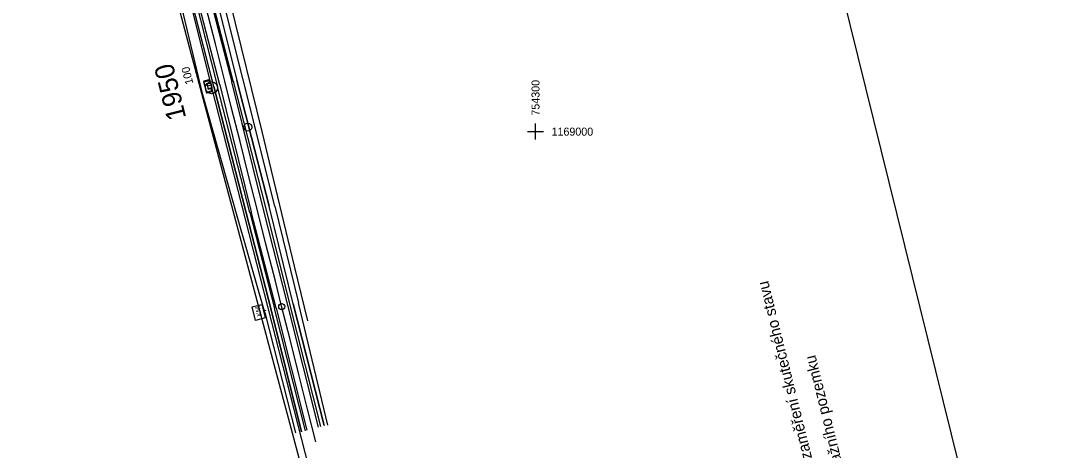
# Model space of a CAD drawing. Extents: x -754679 to -754173, y -1169241 to -1168288.
# Drawn here: x -754428.7 to -754172.8, y -1169079.6 to -1168972.2 of the extents above; entities that cross this region are included whole.
import ezdxf

# ---------------------------------------------------------------- set-up
doc = ezdxf.new("R2010")
doc.units = 0
for name, color, linetype in [('Default', 7, 'Continuous'), ('Vrstva 1', 7, 'Continuous'), ('Vrstva 11', 7, 'Continuous'), ('Vrstva 12', 7, 'Continuous'), ('Vrstva 13', 7, 'Continuous'), ('Vrstva 16', 7, 'Continuous'), ('Vrstva 2', 7, 'Continuous'), ('Vrstva 27', 7, 'Continuous'), ('Vrstva 4', 7, 'Continuous'), ('Vrstva 43', 7, 'Continuous'), ('Vrstva 53', 7, 'Continuous'), ('Vrstva 61', 7, 'Continuous'), ('Vrstva 63', 7, 'Continuous'), ('Vrstva 7', 7, 'Continuous')]:
    doc.layers.add(name, color=color, linetype=linetype)

msp = doc.modelspace()

# ---------------------------------------------------------------- linework, layer by layer
at = {"layer": 'Default'}
for points in [[(-754300, -1169002), (-754300, -1169000), (-754300, -1168998)], [(-754302, -1169000), (-754300, -1169000), (-754298, -1169000)]]:
    msp.add_lwpolyline(points, dxfattribs=at)
at = {"layer": 'Vrstva 1'}
msp.add_line((-754380.95, -1168989.01), (-754380.95, -1168989.01), dxfattribs=at)
for points in [[(-754371.76, -1169010.62), (-754373.81, -1169002.5), (-754376.01, -1168993.77), (-754377.62, -1168987.41), (-754379.98, -1168978.06), (-754382.33, -1168968.78)], [(-754354.86, -1169077.5), (-754356.93, -1169069.33), (-754359.12, -1169060.65), (-754361.33, -1169051.91), (-754363.43, -1169043.59), (-754365, -1169037.37), (-754367.34, -1169028.11), (-754369.54, -1169019.37), (-754371.76, -1169010.62)]]:
    msp.add_lwpolyline(points, dxfattribs=at)
at = {"layer": 'Vrstva 11'}
for p, q in [((-754382.1, -1168988.18), (-754381.86, -1168989.15)), ((-754381.01, -1168988.42), (-754381.98, -1168988.67)), ((-754381.13, -1168987.94), (-754380.89, -1168988.91))]:
    msp.add_line(p, q, dxfattribs=at)
at = {"layer": 'Vrstva 12'}
for p, q in [((-754381.15, -1168987.81), (-754382.14, -1168988.06)), ((-754382.14, -1168988.06), (-754381.78, -1168989.35)), ((-754382.14, -1168988.06), (-754382.11, -1168988.09)), ((-754382.11, -1168988.09), (-754381.18, -1168987.86)), ((-754382.11, -1168988.09), (-754381.76, -1168989.31)), ((-754381.18, -1168987.86), (-754381.15, -1168987.81)), ((-754381.18, -1168987.86), (-754380.87, -1168989.06)), ((-754380.82, -1168989.07), (-754381.15, -1168987.81)), ((-754381.78, -1168989.35), (-754380.82, -1168989.07)), ((-754381.78, -1168989.35), (-754381.76, -1168989.31)), ((-754380.87, -1168989.06), (-754381.76, -1168989.31)), ((-754380.87, -1168989.06), (-754380.82, -1168989.07))]:
    msp.add_line(p, q, dxfattribs=at)
at = {"layer": 'Vrstva 13'}
for p, q in [((-754382.83, -1168987.43), (-754382.97, -1168987.46)), ((-754382.97, -1168987.46), (-754382.21, -1168990.34)), ((-754381.61, -1168987.09), (-754382.83, -1168987.43)), ((-754382.79, -1168987.54), (-754381.57, -1168987.21)), ((-754382.12, -1168990.19), (-754382.79, -1168987.54)), ((-754381.43, -1168987.69), (-754381.61, -1168987.07)), ((-754381.61, -1168987.07), (-754381.61, -1168987.09)), ((-754381.57, -1168987.21), (-754381.58, -1168987.26)), ((-754381.58, -1168987.26), (-754381.47, -1168987.7)), ((-754381.47, -1168987.7), (-754381.43, -1168987.69)), ((-754382.21, -1168990.34), (-754382.07, -1168990.3)), ((-754380.87, -1168989.82), (-754382.12, -1168990.19)), ((-754382.07, -1168990.3), (-754380.83, -1168989.97)), ((-754380.8, -1168989.96), (-754381.01, -1168989.33)), ((-754381.01, -1168989.33), (-754381, -1168989.38)), ((-754381, -1168989.38), (-754380.88, -1168989.81)), ((-754380.88, -1168989.81), (-754380.87, -1168989.82)), ((-754380.83, -1168989.97), (-754380.8, -1168989.96))]:
    msp.add_line(p, q, dxfattribs=at)
at = {"layer": 'Vrstva 16'}
for p, q in [((-754383.09, -1168990.79), (-754389.27, -1168965.03)), ((-754380.4, -1168988.75), (-754386.36, -1168965.6)), ((-754380.26, -1168964.46), (-754374.59, -1168987.21)), ((-754373.15, -1168986.73), (-754378.4, -1168965.63)), ((-754372.32, -1169020.28), (-754380.4, -1168988.75)), ((-754374.59, -1168987.21), (-754366.52, -1169018.6)), ((-754365.15, -1169018.62), (-754373.15, -1168986.73)), ((-754374.58, -1169021.12), (-754383.09, -1168990.79)), ((-754360.51, -1169043.02), (-754366.52, -1169018.6)), ((-754365.15, -1169018.62), (-754359.23, -1169042.75)), ((-754367.66, -1169045.21), (-754374.58, -1169021.12)), ((-754372.32, -1169020.28), (-754366.03, -1169044.49)), ((-754367.66, -1169045.21), (-754359.97, -1169075.19)), ((-754360.51, -1169043.02), (-754352.79, -1169073.4)), ((-754351.91, -1169073.27), (-754359.23, -1169042.75))]:
    msp.add_line(p, q, dxfattribs=at)
msp.add_lwpolyline([(-754358.47, -1169074.96), (-754366.03, -1169044.49)], dxfattribs=at)
at = {"layer": 'Vrstva 4'}
for p, q in [((-754380.4, -1168988.75), (-754386.36, -1168965.6)), ((-754385.5, -1168965.09), (-754379.51, -1168988.47)), ((-754378.9, -1168988.34), (-754384.97, -1168964.92)), ((-754381.82, -1168964.83), (-754375.86, -1168987.58)), ((-754375.55, -1168987.36), (-754381.38, -1168964.7)), ((-754380.26, -1168964.46), (-754374.59, -1168987.21)), ((-754380.4, -1168988.75), (-754372.32, -1169020.28)), ((-754371.4, -1169020.16), (-754379.51, -1168988.47)), ((-754378.9, -1168988.34), (-754371.02, -1169020.06)), ((-754368.08, -1169019.1), (-754375.86, -1168987.58)), ((-754375.55, -1168987.36), (-754367.49, -1169018.94)), ((-754366.52, -1169018.6), (-754374.59, -1168987.21)), ((-754361.88, -1169043.38), (-754368.08, -1169019.1)), ((-754367.49, -1169018.94), (-754361.41, -1169043.35)), ((-754360.51, -1169043.02), (-754366.52, -1169018.6)), ((-754366.03, -1169044.49), (-754372.32, -1169020.28)), ((-754371.4, -1169020.16), (-754365.23, -1169044.2)), ((-754364.82, -1169044.09), (-754371.02, -1169020.06)), ((-754366.03, -1169044.49), (-754358.47, -1169074.96)), ((-754357.5, -1169074.69), (-754365.23, -1169044.2)), ((-754364.82, -1169044.09), (-754357.15, -1169074.54)), ((-754354.18, -1169073.77), (-754361.88, -1169043.38)), ((-754361.41, -1169043.35), (-754353.7, -1169073.61)), ((-754352.79, -1169073.4), (-754360.51, -1169043.02))]:
    msp.add_line(p, q, dxfattribs=at)
at = {"layer": 'Vrstva 43'}
msp.add_circle((-754371.9, -1168998.88), 1, dxfattribs=at)
at = {"layer": 'Vrstva 53'}
for p, q in [((-754378.16, -1168960.13), (-754373.54, -1168979.01)), ((-754373.54, -1168979.01), (-754368.41, -1168999.96)), ((-754368.41, -1168999.96), (-754366.06, -1169009.68)), ((-754366.06, -1169009.68), (-754360.29, -1169033.58)), ((-754360.29, -1169033.58), (-754356.98, -1169047.27))]:
    msp.add_line(p, q, dxfattribs=at)
msp.add_lwpolyline([(-754345.91, -1169130.8), (-754386.06, -1168980.52), (-754394.57, -1168948.26)], dxfattribs=at)
at = {"layer": 'Vrstva 61'}
msp.add_lwpolyline([(-754461.15, -1169240.8), (-754172.83, -1169169.5), (-754273.65, -1168761.78), (-754561.97, -1168833.08)], dxfattribs=at)
at = {"layer": 'Vrstva 63'}
msp.add_line((-754381.05, -1168989.01), (-754380.85, -1168989.01), dxfattribs=at)
msp.add_lwpolyline([(-754409.15, -1168875.91), (-754380.95, -1168989.01), (-754335.99, -1169164.84)], dxfattribs=at)
msp.add_circle((-754380.95, -1168989.01), 1.51, dxfattribs=at)
at = {"layer": 'Vrstva 7'}
msp.add_line((-754367.34, -1169044.69), (-754367.95, -1169044.84), dxfattribs=at)
msp.add_lwpolyline([(-754367.52, -1169046.53), (-754369.93, -1169047.14), (-754370.78, -1169043.76), (-754368.37, -1169043.15)], close=True, dxfattribs=at)
msp.add_circle((-754363.4, -1169043.69), 0.75, dxfattribs=at)

# ---------------------------------------------------------------- texts
at = {"layer": 'Default'}
msp.add_text('754300', height=2, rotation=90, dxfattribs=at).set_placement((-754299, -1168996))
msp.add_text('1169000', height=2, dxfattribs=at).set_placement((-754296, -1169001))
at = {"layer": 'Vrstva 11'}
msp.add_text('100', height=2, rotation=104.1774, dxfattribs=at).set_placement((-754385.47, -1168987.94))
at = {"layer": 'Vrstva 2'}
msp.add_text('1950', height=4.8, rotation=104.0018, dxfattribs=at).set_placement((-754387.24, -1168996.51))
at = {"layer": 'Vrstva 27'}
for s, p in [('geodetické zaměření skutečného stavu', (-754226.28, -1169100.11)), ('hranice drážního pozemku', (-754219.49, -1169098.43))]:
    msp.add_text(s, height=2.8, rotation=103.9106, dxfattribs=at).set_placement(p)
at = {"layer": 'Vrstva 7'}
msp.add_text('KM', height=1.247, rotation=104.1835, dxfattribs=at).set_placement((-754368.3, -1169045.98))

doc.saveas('drawing.dxf')
